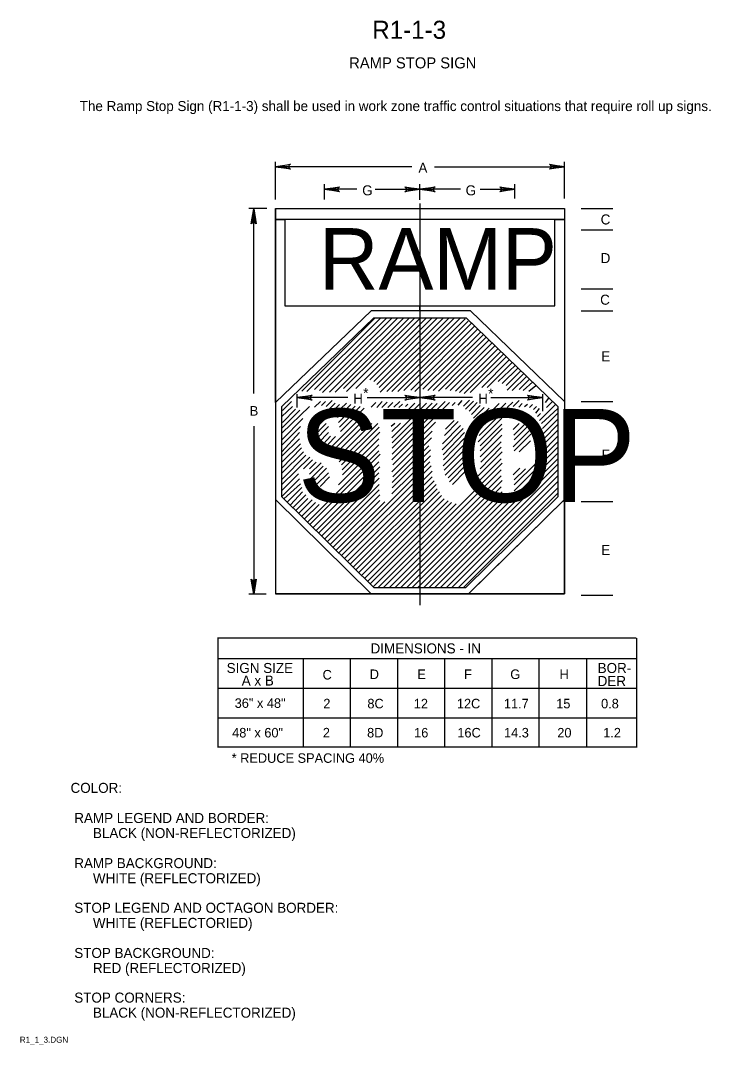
# Model space of a CAD drawing. Extents: x 0.013 to 0.184, y 0.004 to 0.259.
import ezdxf

# ---------------------------------------------------------------- set-up
doc = ezdxf.new("R2010")
doc.units = 0
for name, color, linetype in [('1', 7, 'Continuous'), ('2', 7, 'Continuous'), ('3', 7, 'Continuous')]:
    doc.layers.add(name, color=color, linetype=linetype)

# ---------------------------------------------------------------- blocks, each defined once
blk = doc.blocks.new('RARROW')
at = {"layer": '3'}
for p, q in [((-2.156, 0.285), (-2.2665, 0.384625)), ((-2.2665, 0.384625), (0, 0)), ((0, 0), (-2.2665, -0.379125)), ((-2.156, 0.285), (-2.075625, 0.12075)), ((0, 0), (-2.156, 0.285)), ((-2.14975, -0.2705), (0, 0)), ((-2.075625, 0.12075), (0, 0)), ((0, 0), (-2.074, -0.108)), ((-2.2665, -0.379125), (-2.14975, -0.2705)), ((-2.074, -0.108), (-2.14975, -0.2705))]:
    blk.add_line(p, q, dxfattribs=at)

msp = doc.modelspace()

# ---------------------------------------------------------------- linework, layer by layer
at = {"layer": '1'}
for p, q in [((0.11213, 0.2135), (0.11213, 0.11338)), ((0.0815, 0.166), (0.0815, 0.16262)), ((0.14263, 0.166), (0.14263, 0.16175))]:
    msp.add_line(p, q, dxfattribs=at)
at = {"layer": '3'}
for p, q in [((0.07612, 0.2145), (0.07612, 0.22388)), ((0.11013, 0.22263), (0.07612, 0.22263)), ((0.11575, 0.22263), (0.14813, 0.22263)), ((0.14813, 0.21475), (0.14813, 0.22388)), ((0.08837, 0.2145), (0.08837, 0.21825)), ((0.09638, 0.217), (0.08837, 0.217)), ((0.101, 0.217), (0.11213, 0.217)), ((0.11213, 0.21438), (0.11213, 0.21825)), ((0.12225, 0.217), (0.11213, 0.217)), ((0.12713, 0.217), (0.13575, 0.217)), ((0.13575, 0.21475), (0.13575, 0.21825)), ((0.074, 0.21225), (0.0695, 0.21225)), ((0.07075, 0.16612), (0.07075, 0.21225)), ((0.07612, 0.21225), (0.14813, 0.21225)), ((0.07612, 0.21225), (0.07612, 0.11625)), ((0.14813, 0.21225), (0.14813, 0.11625)), ((0.15225, 0.21225), (0.16012, 0.21225)), ((0.14575, 0.188), (0.14575, 0.2095)), ((0.14575, 0.2095), (0.14813, 0.2095)), ((0.14813, 0.2095), (0.14813, 0.16412)), ((0.15225, 0.20688), (0.16012, 0.20688)), ((0.15225, 0.19225), (0.16012, 0.19225)), ((0.11213, 0.188), (0.14575, 0.188)), ((0.11213, 0.18675), (0.11213, 0.188)), ((0.12475, 0.18675), (0.11213, 0.18675)), ((0.14813, 0.16412), (0.12475, 0.18675)), ((0.14813, 0.16412), (0.12475, 0.18675)), ((0.15225, 0.18675), (0.16012, 0.18675)), ((0.10063, 0.185), (0.07775, 0.16287)), ((0.08275, 0.16675), (0.101, 0.185)), ((0.084, 0.16662), (0.10238, 0.185)), ((0.08588, 0.16712), (0.10388, 0.185)), ((0.08713, 0.16687), (0.10525, 0.185)), ((0.08788, 0.16637), (0.10662, 0.185)), ((0.08962, 0.1665), (0.10812, 0.185)), ((0.091, 0.1665), (0.1095, 0.185)), ((0.09312, 0.16737), (0.11088, 0.185)), ((0.09388, 0.16662), (0.11225, 0.185)), ((0.09613, 0.16737), (0.11375, 0.185)), ((0.09963, 0.1695), (0.11513, 0.185)), ((0.10063, 0.185), (0.12362, 0.185)), ((0.10063, 0.16912), (0.1165, 0.185)), ((0.10138, 0.16837), (0.118, 0.185)), ((0.102, 0.16762), (0.11938, 0.185)), ((0.10225, 0.1665), (0.12075, 0.185)), ((0.10388, 0.16662), (0.12225, 0.185)), ((0.10512, 0.16662), (0.12337, 0.18475)), ((0.10662, 0.16662), (0.12412, 0.18413)), ((0.12362, 0.185), (0.1465, 0.16287)), ((0.10812, 0.16687), (0.125, 0.18363)), ((0.10988, 0.167), (0.12575, 0.18288)), ((0.11088, 0.16662), (0.1265, 0.18225)), ((0.11288, 0.16725), (0.12725, 0.1815)), ((0.11413, 0.16687), (0.128, 0.18088)), ((0.11538, 0.16687), (0.12862, 0.18013)), ((0.11675, 0.16675), (0.12937, 0.1795)), ((0.1185, 0.16725), (0.13012, 0.17875)), ((0.11963, 0.16687), (0.13075, 0.178)), ((0.121, 0.16675), (0.13162, 0.17738)), ((0.122, 0.16637), (0.13225, 0.17663)), ((0.12312, 0.16612), (0.133, 0.176)), ((0.12462, 0.16637), (0.13362, 0.17525)), ((0.1275, 0.16762), (0.13437, 0.1745)), ((0.12887, 0.16762), (0.13512, 0.17388)), ((0.13162, 0.16912), (0.13587, 0.17313)), ((0.13262, 0.16862), (0.13662, 0.1725)), ((0.13362, 0.16812), (0.13725, 0.17175)), ((0.13387, 0.167), (0.138, 0.17112)), ((0.13512, 0.16687), (0.13862, 0.17037)), ((0.13687, 0.16712), (0.1395, 0.16975)), ((0.13787, 0.16687), (0.14025, 0.169)), ((0.13925, 0.16675), (0.141, 0.16812)), ((0.07787, 0.16187), (0.08013, 0.16412)), ((0.09413, 0.16512), (0.0815, 0.16512)), ((0.08588, 0.16275), (0.08738, 0.16412)), ((0.08763, 0.16312), (0.08862, 0.16412)), ((0.08875, 0.16287), (0.09025, 0.16437)), ((0.0895, 0.16225), (0.091, 0.16375)), ((0.09062, 0.16187), (0.09212, 0.16337)), ((0.09087, 0.16087), (0.09388, 0.16375)), ((0.09162, 0.16012), (0.09488, 0.16337)), ((0.099, 0.16512), (0.11213, 0.16512)), ((0.1, 0.16275), (0.10113, 0.16387)), ((0.10138, 0.16262), (0.10275, 0.16412)), ((0.10263, 0.16262), (0.104, 0.164)), ((0.10412, 0.16262), (0.10537, 0.16387)), ((0.10512, 0.14963), (0.1195, 0.16387)), ((0.10512, 0.15513), (0.11375, 0.16375)), ((0.10525, 0.151), (0.11838, 0.16412)), ((0.10525, 0.15388), (0.11513, 0.16375)), ((0.10525, 0.1525), (0.11638, 0.16362)), ((0.10562, 0.16275), (0.10712, 0.16412)), ((0.10687, 0.16262), (0.10775, 0.1635)), ((0.1085, 0.16287), (0.10912, 0.1635)), ((0.10912, 0.162), (0.11088, 0.16375)), ((0.10938, 0.16087), (0.11225, 0.16375)), ((0.12525, 0.16512), (0.11213, 0.16512)), ((0.12012, 0.16312), (0.12087, 0.16387)), ((0.12162, 0.16325), (0.12262, 0.16437)), ((0.123, 0.163), (0.1245, 0.1645)), ((0.1235, 0.16225), (0.1255, 0.16425)), ((0.12437, 0.16175), (0.12638, 0.16387)), ((0.12625, 0.158), (0.13187, 0.16362)), ((0.12663, 0.15688), (0.1335, 0.16375)), ((0.12975, 0.16512), (0.14263, 0.16512)), ((0.13387, 0.16262), (0.13525, 0.164)), ((0.13537, 0.16287), (0.13687, 0.16437)), ((0.13675, 0.16275), (0.13762, 0.16362)), ((0.13812, 0.16287), (0.13887, 0.1635)), ((0.13937, 0.16262), (0.14012, 0.16337)), ((0.14188, 0.15938), (0.14588, 0.16337)), ((0.14338, 0.16387), (0.14425, 0.165)), ((0.14363, 0.16262), (0.14513, 0.16412)), ((0.15225, 0.16412), (0.16012, 0.16412)), ((0.07775, 0.14037), (0.07775, 0.16287)), ((0.07775, 0.15625), (0.08463, 0.16287)), ((0.07775, 0.16037), (0.08038, 0.16287)), ((0.07775, 0.1575), (0.08225, 0.162)), ((0.07787, 0.15888), (0.08113, 0.16225)), ((0.09187, 0.15888), (0.096, 0.163)), ((0.09212, 0.15775), (0.09725, 0.16287)), ((0.09237, 0.15663), (0.09825, 0.1625)), ((0.125, 0.16087), (0.12713, 0.16312)), ((0.1255, 0.16), (0.12812, 0.16262)), ((0.12588, 0.15913), (0.12937, 0.1625)), ((0.12688, 0.15563), (0.13262, 0.16137)), ((0.14037, 0.16212), (0.14113, 0.16287)), ((0.141, 0.16125), (0.14188, 0.16237)), ((0.14138, 0.16037), (0.14213, 0.16112)), ((0.14238, 0.15863), (0.1465, 0.16237)), ((0.14263, 0.15738), (0.1465, 0.16125)), ((0.1465, 0.16287), (0.1465, 0.14037)), ((0.07775, 0.15463), (0.083, 0.15988)), ((0.085, 0.15625), (0.08812, 0.15938)), ((0.08525, 0.15513), (0.08875, 0.15863)), ((0.08987, 0.15263), (0.09788, 0.16062)), ((0.09087, 0.15225), (0.098, 0.15938)), ((0.09137, 0.15138), (0.09863, 0.15863)), ((0.092, 0.14913), (0.10163, 0.15863)), ((0.09225, 0.15075), (0.10013, 0.15863)), ((0.105, 0.158), (0.10587, 0.15875)), ((0.10512, 0.15663), (0.10725, 0.15875)), ((0.10537, 0.14838), (0.116, 0.159)), ((0.11825, 0.15563), (0.12162, 0.15913)), ((0.1185, 0.15725), (0.12062, 0.15938)), ((0.12663, 0.15413), (0.1325, 0.16)), ((0.12713, 0.15313), (0.1325, 0.1585)), ((0.13537, 0.15713), (0.13687, 0.15863)), ((0.1355, 0.15575), (0.13825, 0.1585)), ((0.14263, 0.15588), (0.1465, 0.15975)), ((0.14288, 0.15475), (0.1465, 0.15838)), ((0.07075, 0.158), (0.07075, 0.11625)), ((0.07775, 0.15325), (0.08238, 0.15788)), ((0.07775, 0.15163), (0.08213, 0.15638)), ((0.08588, 0.15438), (0.08937, 0.15788)), ((0.08688, 0.15388), (0.08937, 0.15638)), ((0.09262, 0.14838), (0.102, 0.15775)), ((0.09275, 0.14713), (0.10213, 0.1565)), ((0.10512, 0.14663), (0.11513, 0.15675)), ((0.11763, 0.15213), (0.12287, 0.15738)), ((0.11775, 0.15363), (0.12225, 0.15813)), ((0.11788, 0.15088), (0.12325, 0.15638)), ((0.12713, 0.15188), (0.13262, 0.15738)), ((0.12713, 0.15038), (0.1325, 0.15575)), ((0.13537, 0.15288), (0.1395, 0.157)), ((0.13562, 0.15463), (0.13887, 0.15788)), ((0.13562, 0.15188), (0.13975, 0.156)), ((0.14275, 0.15325), (0.1465, 0.157)), ((0.07775, 0.1505), (0.08213, 0.15488)), ((0.07775, 0.149), (0.08238, 0.15363)), ((0.08812, 0.15363), (0.08987, 0.1555)), ((0.08925, 0.1535), (0.09112, 0.15538)), ((0.09187, 0.14338), (0.10188, 0.15338)), ((0.09287, 0.14588), (0.10188, 0.15488)), ((0.10525, 0.144), (0.11438, 0.15313)), ((0.10537, 0.14538), (0.115, 0.15513)), ((0.11788, 0.14813), (0.12375, 0.154)), ((0.118, 0.14963), (0.1235, 0.15525)), ((0.12725, 0.149), (0.13237, 0.15413)), ((0.13562, 0.14338), (0.1465, 0.15413)), ((0.13687, 0.15163), (0.13962, 0.15438)), ((0.14213, 0.15113), (0.1465, 0.1555)), ((0.07775, 0.1475), (0.08263, 0.15263)), ((0.07775, 0.14625), (0.08313, 0.15163)), ((0.07775, 0.14475), (0.08375, 0.15075)), ((0.08413, 0.13412), (0.10188, 0.15188)), ((0.08475, 0.1335), (0.10225, 0.151)), ((0.10512, 0.14113), (0.11475, 0.15063)), ((0.10525, 0.14263), (0.11475, 0.15213)), ((0.11813, 0.147), (0.124, 0.15288)), ((0.11838, 0.14575), (0.12387, 0.15125)), ((0.12638, 0.14538), (0.13262, 0.15163)), ((0.12713, 0.14738), (0.13237, 0.15275)), ((0.13562, 0.14188), (0.1465, 0.15275)), ((0.13562, 0.14037), (0.1465, 0.15125)), ((0.07775, 0.1435), (0.08475, 0.15025)), ((0.08313, 0.14738), (0.08538, 0.14963)), ((0.08463, 0.14738), (0.08625, 0.149)), ((0.08463, 0.146), (0.0875, 0.14888)), ((0.08488, 0.14488), (0.088, 0.148)), ((0.0855, 0.13275), (0.10188, 0.14913)), ((0.09187, 0.12638), (0.11463, 0.14913)), ((0.09262, 0.12575), (0.11488, 0.14813)), ((0.10163, 0.11775), (0.13262, 0.14875)), ((0.11438, 0.11775), (0.1465, 0.14988)), ((0.11575, 0.11775), (0.1465, 0.1485)), ((0.11913, 0.14513), (0.12387, 0.14988)), ((0.1195, 0.14413), (0.12387, 0.14863)), ((0.1255, 0.143), (0.13237, 0.14988)), ((0.07775, 0.142), (0.08188, 0.14613)), ((0.08525, 0.14388), (0.08887, 0.1475)), ((0.08625, 0.132), (0.10213, 0.14788)), ((0.08625, 0.14338), (0.08937, 0.14638)), ((0.08688, 0.13137), (0.10188, 0.14638)), ((0.09337, 0.125), (0.11513, 0.14675)), ((0.103, 0.11775), (0.13237, 0.14713)), ((0.1045, 0.11775), (0.13237, 0.14563)), ((0.11713, 0.11775), (0.1465, 0.14713)), ((0.11863, 0.11775), (0.1465, 0.14563)), ((0.12025, 0.1435), (0.1235, 0.14675)), ((0.13537, 0.14588), (0.137, 0.1475)), ((0.13562, 0.14463), (0.13837, 0.14738)), ((0.07775, 0.1405), (0.08213, 0.14488)), ((0.07825, 0.13987), (0.08238, 0.14363)), ((0.08725, 0.143), (0.08962, 0.14538)), ((0.08763, 0.13062), (0.102, 0.145)), ((0.08837, 0.12987), (0.102, 0.1435)), ((0.09413, 0.12437), (0.11513, 0.14538)), ((0.09475, 0.12362), (0.11563, 0.14438)), ((0.0955, 0.12287), (0.11613, 0.1435)), ((0.10587, 0.11775), (0.13262, 0.1445)), ((0.10725, 0.11775), (0.13237, 0.14288)), ((0.12, 0.11775), (0.1465, 0.14425)), ((0.07775, 0.14037), (0.10075, 0.11775)), ((0.07913, 0.13912), (0.08275, 0.14275)), ((0.07988, 0.13837), (0.08288, 0.14163)), ((0.0805, 0.13762), (0.08375, 0.14088)), ((0.08912, 0.12925), (0.102, 0.14213)), ((0.08975, 0.1285), (0.10213, 0.14088)), ((0.09625, 0.12225), (0.11638, 0.14238)), ((0.09688, 0.1215), (0.117, 0.14163)), ((0.09763, 0.12087), (0.1175, 0.14075)), ((0.10875, 0.11775), (0.13262, 0.14163)), ((0.12162, 0.11775), (0.1465, 0.14263)), ((0.12287, 0.11775), (0.14638, 0.14125)), ((0.1465, 0.14037), (0.1235, 0.11775)), ((0.07612, 0.13975), (0.1, 0.11625)), ((0.1, 0.11625), (0.07612, 0.13975)), ((0.07612, 0.13975), (0.07612, 0.11625)), ((0.08125, 0.137), (0.08425, 0.14)), ((0.08188, 0.13625), (0.08525, 0.13962)), ((0.08263, 0.1355), (0.08613, 0.139)), ((0.08338, 0.13487), (0.087, 0.1385)), ((0.0905, 0.12788), (0.10213, 0.1395)), ((0.09125, 0.12713), (0.10338, 0.13912)), ((0.09838, 0.12012), (0.11813, 0.13987)), ((0.09913, 0.11938), (0.11913, 0.13937)), ((0.09975, 0.11875), (0.12, 0.139)), ((0.1005, 0.118), (0.12112, 0.13862)), ((0.11013, 0.11775), (0.13237, 0.14)), ((0.1115, 0.11775), (0.13312, 0.13937)), ((0.113, 0.11775), (0.13462, 0.13937)), ((0.14813, 0.13975), (0.12425, 0.11625)), ((0.15225, 0.13925), (0.16012, 0.13925)), ((0.1235, 0.11775), (0.10075, 0.11775)), ((0.07387, 0.11613), (0.0695, 0.11613)), ((0.14813, 0.11625), (0.07612, 0.11625)), ((0.07612, 0.11625), (0.1, 0.11625)), ((0.1, 0.11625), (0.14813, 0.11625)), ((0.15225, 0.11588), (0.16012, 0.11588)), ((0.06175, 0.10525), (0.166, 0.10525)), ((0.06181, 0.10515), (0.06181, 0.07797)), ((0.16606, 0.10515), (0.16606, 0.07797)), ((0.166, 0.1), (0.06175, 0.1)), ((0.08306, 0.0999), (0.08306, 0.07797)), ((0.09475, 0.1), (0.09475, 0.078)), ((0.1065, 0.1), (0.1065, 0.078)), ((0.11825, 0.1), (0.11825, 0.078)), ((0.13, 0.1), (0.13, 0.078)), ((0.14175, 0.1), (0.14175, 0.078)), ((0.15356, 0.0999), (0.15356, 0.07797)), ((0.15356, 0.0999), (0.15356, 0.07965)), ((0.166, 0.09262), (0.06175, 0.09262)), ((0.166, 0.08525), (0.06175, 0.08525)), ((0.166, 0.078), (0.06175, 0.078))]:
    msp.add_line(p, q, dxfattribs=at)
for points in [[(0.07612, 0.21225), (0.14813, 0.21225), (0.14813, 0.2095), (0.07612, 0.2095)], [(0.0785, 0.2095), (0.0785, 0.188), (0.11213, 0.188), (0.11213, 0.18675), (0.09999, 0.18675), (0.07612, 0.16387), (0.07612, 0.2095)], [(0.1285, 0.11625), (0.14813, 0.11625), (0.14813, 0.13975), (0.125, 0.117), (0.12425, 0.11625)]]:
    msp.add_lwpolyline(points, close=True, dxfattribs=at)

# ---------------------------------------------------------------- block references
at = {"layer": '3', "xscale": 0.0016545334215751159, "yscale": 0.0016366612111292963}
for p, rotation in [((0.07612, 0.22263), 180), ((0.08837, 0.217), 180), ((0.11213, 0.217), 180), ((0.07075, 0.21213), 90), ((0.0815, 0.16512), 180), ((0.11213, 0.16512), 180), ((0.07075, 0.11613), -90)]:
    msp.add_blockref('RARROW', p, dxfattribs=dict(at, rotation=rotation))
for p in [(0.14813, 0.22263), (0.11213, 0.217), (0.13575, 0.217), (0.11213, 0.16512), (0.14263, 0.16512)]:
    msp.add_blockref('RARROW', p, dxfattribs=at)

# ---------------------------------------------------------------- texts
at = {"layer": '1'}
for s, height, p in [('R1-1-3', 0.0045, (0.10025, 0.2545)), ('RAMP STOP SIGN', 0.0027503, (0.0945, 0.24713)), ('COLOR:', 0.0025, (0.02513, 0.06663)), (' RAMP LEGEND AND BORDER:', 0.0024998, (0.02513, 0.05913)), ('      BLACK (NON-REFLECTORIZED)', 0.0024998, (0.02513, 0.05538)), (' RAMP BACKGROUND:', 0.0024998, (0.02513, 0.04788)), ('      WHITE (REFLECTORIZED)', 0.0024998, (0.02513, 0.04412)), (' STOP LEGEND AND OCTAGON BORDER:', 0.0024998, (0.02513, 0.03675)), ('      WHITE (REFLECTORIED)', 0.0024998, (0.02513, 0.033)), (' STOP BACKGROUND:', 0.0024998, (0.02513, 0.0255)), ('      RED (REFLECTORIZED)', 0.0024998, (0.02513, 0.02175)), (' STOP CORNERS:', 0.0024998, (0.02513, 0.01438)), ('      BLACK (NON-REFLECTORIZED)', 0.0024998, (0.02513, 0.01063)), ('R1_1_3.DGN', 0.0015, (0.0125, 0.00438))]:
    msp.add_text(s, height=height, dxfattribs=at).set_placement(p)
at = {"layer": '2'}
msp.add_text('   The Ramp Stop Sign (R1-1-3) shall be used in work zone traffic control situations that require roll up signs.', height=0.00249975, dxfattribs=at).set_placement((0.02463, 0.2365))
at = {"layer": '3'}
for s, height, p in [('A', 0.0025, (0.11175, 0.22113)), ('G', 0.0025, (0.09775, 0.2155)), ('G', 0.0025, (0.1235, 0.2155)), ('C', 0.0025, (0.15713, 0.20825)), ('RAMP', 0.01533, (0.087, 0.192)), ('D', 0.0025, (0.15713, 0.19862)), ('C', 0.0025, (0.157, 0.18825)), ('E', 0.0025, (0.15725, 0.17413)), ('H', 0.0025, (0.0955, 0.16362)), ('*', 0.0025, (0.098, 0.165)), ('H', 0.0025, (0.12663, 0.16362)), ('*', 0.0025, (0.12912, 0.16487)), ('B', 0.00238, (0.06975, 0.16062)), ('STOP', 0.023156, (0.08163, 0.13912)), ('F', 0.0025, (0.15738, 0.14963)), ('E', 0.0025, (0.15725, 0.12588)), ('DIMENSIONS - IN', 0.0024998, (0.09983, 0.10138)), ('SIGN SIZE', 0.0025, (0.064, 0.0965)), ('C', 0.00238, (0.08788, 0.09488)), ('D', 0.00238, (0.09963, 0.095)), ('E', 0.00238, (0.1115, 0.095)), ('F', 0.00238, (0.12312, 0.095)), ('G', 0.00238, (0.13462, 0.095)), ('H', 0.00238, (0.14688, 0.095)), ('BOR-', 0.0025, (0.15638, 0.0965)), ('A x B', 0.0025, (0.06775, 0.09337)), ('DER', 0.0025, (0.15638, 0.09325)), ('36" x 48"', 0.002375, (0.066, 0.08781)), ('2', 0.00238, (0.08807, 0.08769)), ('8C', 0.002375, (0.09904, 0.08769)), ('12', 0.002375, (0.1106, 0.08769)), ('12C', 0.002375, (0.12132, 0.08769)), ('11.7', 0.002375, (0.13303, 0.08769)), ('15', 0.002375, (0.14606, 0.08769)), ('0.8', 0.002375, (0.15723, 0.08769)), ('48" x 60"', 0.002375, (0.06537, 0.08044)), ('2', 0.00238, (0.08795, 0.08044)), ('8D', 0.002375, (0.09897, 0.08044)), ('16', 0.002375, (0.11068, 0.08044)), ('16C', 0.002375, (0.12144, 0.08044)), ('14.3', 0.002375, (0.13306, 0.08044)), ('20', 0.002375, (0.14633, 0.08044)), ('1.2', 0.002375, (0.15776, 0.08044)), ('* REDUCE SPACING 40%', 0.0023752, (0.06525, 0.07412))]:
    msp.add_text(s, height=height, dxfattribs=at).set_placement(p)

doc.saveas('drawing.dxf')
